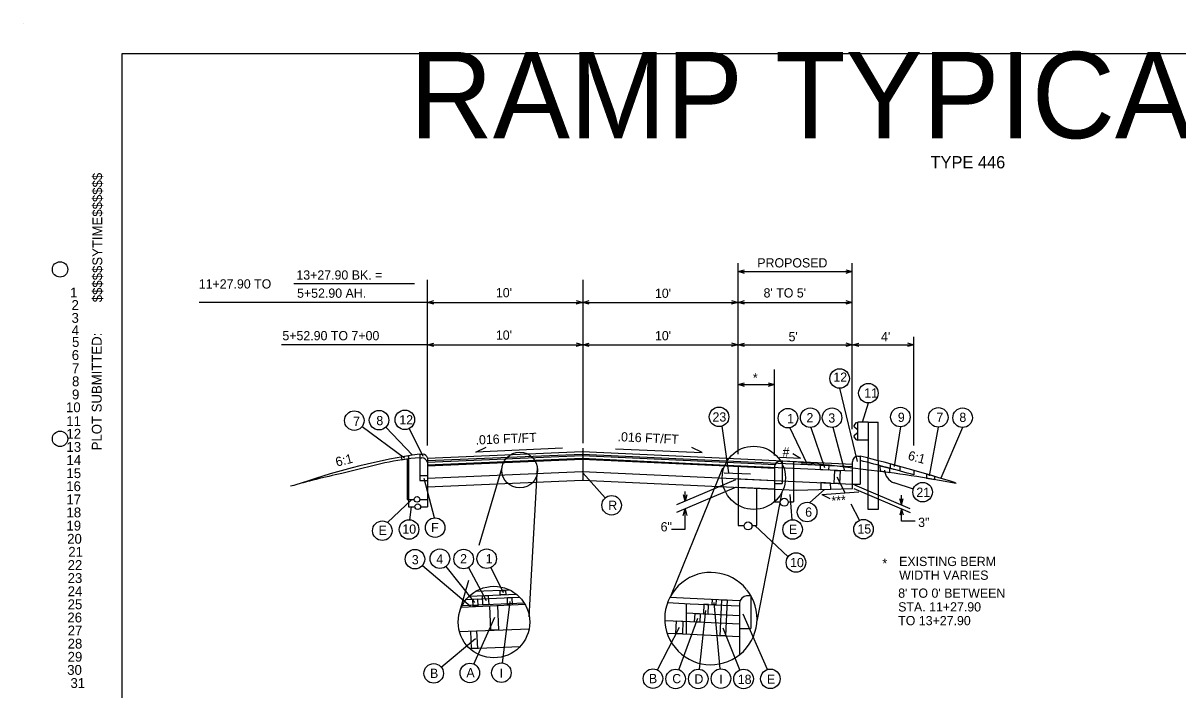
# Model space of a CAD drawing. Extents: x -210 to 558, y -150 to 205.
# Drawn here: x 417 to 491.9, y -105.6 to -62.3 of the extents above; entities that cross this region are included whole.
import ezdxf

# ---------------------------------------------------------------- set-up
doc = ezdxf.new("R2010")
doc.units = 0
for name, color, linetype in [('Level 1', 7, 'Continuous'), ('Level 10', 7, 'Continuous'), ('Level 11', 7, 'Continuous'), ('Level 12', 7, 'Continuous'), ('Level 13', 7, 'Continuous'), ('Level 14', 7, 'Continuous'), ('Level 15', 7, 'Continuous'), ('Level 16', 7, 'Continuous'), ('Level 17', 7, 'Continuous'), ('Level 18', 7, 'Continuous'), ('Level 19', 7, 'Continuous'), ('Level 2', 7, 'Continuous'), ('Level 20', 7, 'Continuous'), ('Level 21', 7, 'Continuous'), ('Level 22', 7, 'Continuous'), ('Level 23', 7, 'Continuous'), ('Level 24', 7, 'Continuous'), ('Level 25', 7, 'Continuous'), ('Level 26', 7, 'Continuous'), ('Level 27', 7, 'Continuous'), ('Level 28', 7, 'Continuous'), ('Level 29', 7, 'Continuous'), ('Level 3', 7, 'Continuous'), ('Level 30', 7, 'Continuous'), ('Level 31', 7, 'Continuous'), ('Level 4', 7, 'Continuous'), ('Level 5', 7, 'Continuous'), ('Level 6', 7, 'Continuous'), ('Level 60', 7, 'Continuous'), ('Level 7', 7, 'Continuous'), ('Level 8', 7, 'Continuous'), ('Level 9', 7, 'Continuous')]:
    doc.layers.add(name, color=color, linetype=linetype)

msp = doc.modelspace()

# ---------------------------------------------------------------- linework, layer by layer
at = {"layer": 'Level 1'}
for p, q in [((417.012, -62.346), (417.012, -62.346)), ((557.356, -64.342), (423.408, -64.342)), ((423.408, -64.342), (423.408, -148.31))]:
    msp.add_line(p, q, dxfattribs=at)
for centre in [(419.41, -78.338), (419.41, -89.334)]:
    msp.add_circle(centre, 0.5, dxfattribs=at)
at = {"layer": 'Level 4'}
for p, q in [((463.4, -90.325), (463.4, -77.927)), ((463.4, -78.481), (470.812, -78.481)), ((470.808, -88.7), (470.808, -77.927)), ((442.408, -79.277), (434.587, -79.277)), ((443.243, -89.772), (443.243, -79.016)), ((453.322, -79.016), (453.322, -89.621)), ((443.243, -80.474), (428.444, -80.474)), ((443.243, -80.474), (453.322, -80.474)), ((453.322, -80.474), (463.4, -80.474)), ((463.4, -80.474), (470.812, -80.474)), ((474.808, -89.766), (474.808, -82.721)), ((443.243, -83.229), (433.787, -83.229)), ((443.243, -83.229), (453.322, -83.229)), ((453.322, -83.229), (474.808, -83.229)), ((465.771, -90.414), (465.771, -84.843)), ((463.397, -85.818), (465.771, -85.818)), ((469.987, -86.052), (471.119, -90.807)), ((471.477, -88.258), (471.853, -87.003)), ((439.008, -88.531), (441.765, -90.578)), ((440.545, -88.584), (442.271, -90.4)), ((442.062, -88.667), (442.951, -90.466)), ((462.337, -88.519), (462.773, -91.547)), ((466.763, -88.61), (467.866, -90.932)), ((468.131, -88.593), (469.015, -91.201)), ((469.541, -88.573), (470.296, -91.411)), ((473.93, -88.552), (473.525, -91.127)), ((476.39, -88.576), (475.801, -91.743)), ((477.968, -88.599), (476.564, -91.891)), ((446.39, -90.191), (447.055, -89.872)), ((461.063, -90.226), (460.398, -89.906)), ((452.016, -89.939), (446.39, -90.191)), ((455.437, -89.974), (461.063, -90.226)), ((467.455, -90.61), (466.956, -90.313)), ((443.696, -94.467), (443.034, -91.907)), ((454.776, -93.175), (453.332, -91.534)), ((463.244, -91.993), (459.409, -93.625)), ((470.352, -92.832), (469.835, -91.829)), ((463.276, -92.477), (459.409, -94.122)), ((459.963, -93.389), (459.963, -92.76)), ((469.013, -92.618), (468.054, -93.476)), ((468.837, -92.94), (471.231, -92.769)), ((470.916, -92.557), (474.561, -94.107)), ((470.947, -92.328), (474.551, -93.862)), ((474.772, -92.594), (473.531, -92.194)), ((442.238, -93.276), (440.663, -94.767)), ((466.758, -92.944), (466.878, -94.587)), ((468.837, -92.94), (469.352, -93.204)), ((471.276, -94.624), (470.738, -93.58)), ((473.997, -93.626), (473.997, -92.996)), ((442.198, -93.739), (442.09, -94.584)), ((459.963, -95.197), (459.963, -93.887)), ((474.007, -94.687), (474.007, -93.872)), ((464.486, -94.97), (466.651, -96.984)), ((474.883, -94.687), (474.007, -94.687)), ((459.087, -95.197), (459.963, -95.197)), ((442.922, -97.555), (446.045, -100.195)), ((444.446, -97.613), (446.294, -99.966)), ((445.9, -97.696), (447.057, -99.824)), ((447.367, -97.686), (448.156, -99.315)), ((448.122, -103.888), (448.611, -99.892)), ((462.236, -104.268), (461.852, -99.952)), ((446.258, -103.952), (447.614, -100.91)), ((459.566, -104.325), (460.784, -100.984)), ((460.903, -104.292), (461.299, -100.481)), ((465.303, -104.308), (463.74, -100.716)), ((458.17, -104.336), (459.602, -101.552)), ((463.52, -104.332), (462.434, -101.631)), ((444.14, -104.156), (446.363, -102.303))]:
    msp.add_line(p, q, dxfattribs=at)
for points in [[(463.82, -78.597), (463.4, -78.481), (463.82, -78.369)], [(463.82, -78.597), (463.4, -78.481), (463.82, -78.369)], [(470.392, -78.365), (470.812, -78.481), (470.392, -78.593)], [(443.663, -80.59), (443.243, -80.474), (443.663, -80.362)], [(452.902, -80.358), (453.322, -80.474), (452.902, -80.586)], [(453.742, -80.59), (453.322, -80.474), (453.742, -80.362)], [(462.98, -80.358), (463.4, -80.474), (462.98, -80.586)], [(463.82, -80.59), (463.4, -80.474), (463.82, -80.362)], [(470.392, -80.358), (470.812, -80.474), (470.392, -80.586)], [(443.663, -83.345), (443.243, -83.229), (443.663, -83.117)], [(452.902, -83.113), (453.322, -83.229), (452.902, -83.341)], [(453.742, -83.345), (453.322, -83.229), (453.742, -83.117)], [(462.98, -83.113), (463.4, -83.229), (462.98, -83.341)], [(463.82, -83.345), (463.4, -83.229), (463.82, -83.117)], [(470.392, -83.113), (470.812, -83.229), (470.392, -83.341)], [(471.232, -83.345), (470.812, -83.229), (471.232, -83.117)], [(474.388, -83.113), (474.808, -83.229), (474.388, -83.341)], [(463.817, -85.934), (463.397, -85.818), (463.817, -85.706)], [(465.351, -85.702), (465.771, -85.818), (465.351, -85.93)], [(460.079, -92.969), (459.963, -93.389), (459.851, -92.969)], [(473.881, -93.206), (473.997, -93.626), (474.109, -93.206)], [(459.847, -94.307), (459.963, -93.887), (460.075, -94.307)], [(474.123, -94.292), (474.007, -93.872), (473.895, -94.292)]]:
    msp.add_lwpolyline(points, dxfattribs=at)
for points in [[(472.624, -91.079), (473.226, -91.243), (473.226, -91.535), (472.635, -91.442)], [(473.284, -90.964), (473.886, -91.128), (473.886, -91.42), (473.284, -91.255)], [(475.627, -91.622), (475.627, -91.888), (476.162, -91.978), (476.162, -91.78)]]:
    msp.add_lwpolyline(points, close=True, dxfattribs=at)
for centre in [(469.988, -85.418), (471.854, -86.369), (438.5, -88.151), (440.108, -88.124), (441.782, -88.098), (462.164, -87.909), (466.634, -87.989), (468.081, -87.961), (469.496, -87.961), (473.931, -87.918), (476.392, -87.941), (477.969, -87.965), (475.374, -92.794), (455.195, -93.65), (467.879, -94.086), (440.318, -95.298), (442.052, -95.216), (443.745, -95.1), (466.94, -95.218), (471.54, -95.201), (442.437, -97.145), (444.055, -97.115), (445.597, -97.139), (447.091, -97.115), (467.158, -97.365), (443.653, -104.562), (446, -104.531), (448.045, -104.517), (457.88, -104.9), (459.349, -104.921), (460.819, -104.921), (462.289, -104.9), (463.757, -104.92), (465.497, -104.912)]:
    msp.add_circle(centre, 0.634, dxfattribs=at)
msp.add_arc((473.861, -91.285), 0.967, 184.63452, 250.04639, dxfattribs=at)
at = {"layer": 'Level 6'}
for p, q in [((441.934, -90.638), (441.934, -93.276)), ((442.743, -90.56), (442.743, -92.038)), ((442.743, -90.56), (442.879, -90.56)), ((443.243, -90.842), (453.277, -90.417)), ((443.243, -91.082), (453.277, -90.657)), ((453.277, -90.417), (463.577, -90.896)), ((453.277, -90.657), (463.577, -91.137)), ((453.322, -89.934), (453.322, -92.019)), ((443.243, -90.862), (443.243, -93.276)), ((463.577, -90.896), (465.805, -91)), ((463.577, -91.137), (465.771, -91.239)), ((465.771, -91.112), (465.771, -93.426)), ((466.092, -90.781), (466.271, -90.781)), ((466.271, -90.781), (466.271, -92.239)), ((466.991, -90.833), (466.991, -93.426)), ((442.743, -92.038), (443.243, -92.038)), ((443.243, -91.88), (453.277, -91.455)), ((443.243, -92.446), (453.277, -92.021)), ((453.277, -91.455), (463.564, -91.934)), ((453.277, -92.021), (463.577, -92.5)), ((463.577, -91.934), (465.771, -92.036)), ((463.577, -92.5), (465.771, -92.603)), ((465.771, -92.239), (466.271, -92.239)), ((441.934, -93.276), (442.388, -93.276)), ((442.752, -93.276), (443.243, -93.276)), ((465.771, -93.426), (466.149, -93.426)), ((466.651, -93.426), (466.991, -93.426)), ((445.766, -99.757), (449.226, -99.61)), ((458.978, -99.623), (460.29, -99.684)), ((463.957, -99.515), (464.218, -99.515)), ((464.218, -99.515), (464.218, -101.642)), ((445.456, -100.251), (449.577, -100.077)), ((458.826, -99.967), (460.29, -100.035)), ((460.033, -100.023), (460.033, -102.012)), ((460.29, -99.684), (463.489, -99.833)), ((460.29, -100.035), (463.489, -100.184)), ((463.489, -99.997), (463.489, -103.372)), ((458.643, -101.12), (460.271, -101.196)), ((460.039, -100.638), (463.489, -100.799)), ((445.325, -101.851), (449.842, -101.66)), ((460.29, -101.197), (463.489, -101.346)), ((463.489, -101.642), (464.218, -101.642)), ((458.796, -101.953), (460.29, -102.023)), ((460.29, -102.023), (463.489, -102.172)), ((446.009, -102.955), (449.254, -102.817))]:
    msp.add_line(p, q, dxfattribs=at)
for centre, radius in [((442.57, -93.265), 0.183), ((466.399, -93.45), 0.257)]:
    msp.add_circle(centre, radius, dxfattribs=at)
for centre, radius, start, end in [((443.889, -105.775), 15.258, 94.30571, 102.86857), ((442.849, -90.967), 0.408, 14.97536, 85.79093), ((459.798, -175.158), 86.442, 102.90634, 104.82046), ((466.162, -91.17), 0.395, 100.20654, 171.53644), ((461.03, -167.839), 77.236, 82.0675, 86.10885), ((462.657, -170.865), 80.034, 79.27032, 83.52075), ((445.323, -129.415), 38.586, 101.4135, 106.49516), ((464.059, -100.083), 0.576, 100.20654, 171.53644)]:
    msp.add_arc(centre, radius, start, end, dxfattribs=at)
at = {"layer": 'Level 60'}
for points in [[(441.594, -90.69), (441.775, -90.664), (441.981, -90.637), (442.032, -90.63), (442.007, -90.441), (441.532, -90.523)], [(467.557, -90.985), (467.563, -90.843), (468.166, -90.871), (468.159, -91.013)], [(468.743, -91.339), (468.756, -91.041), (469.289, -91.066), (469.275, -91.364)], [(469.643, -92.217), (469.682, -91.383), (470.028, -91.399), (469.989, -92.233)], [(468.777, -92.624), (469.424, -92.606), (469.402, -92.206), (468.764, -92.176)], [(446.846, -100.116), (446.821, -99.519), (447.196, -99.503), (447.222, -100.1)], [(447.97, -99.47), (447.958, -99.186), (448.31, -99.172), (448.322, -99.455)], [(448.451, -100.125), (448.43, -99.644), (448.73, -99.631), (448.75, -100.112)], [(446.221, -100.219), (446.2, -99.738), (446.489, -99.726), (446.51, -100.207)], [(447.367, -101.765), (447.3, -100.173), (447.784, -100.153), (447.851, -101.744)], [(461.187, -100.075), (461.158, -100.696), (461.451, -100.71), (461.48, -100.088)], [(461.73, -100.102), (461.747, -99.752), (461.97, -99.762), (461.954, -100.112)], [(462.228, -102.113), (462.336, -99.779), (462.683, -99.795), (462.575, -102.129)], [(460.583, -101.214), (460.608, -100.668), (460.945, -100.684), (460.919, -101.23)], [(446.106, -102.951), (446.058, -101.82), (446.436, -101.804), (446.484, -102.935)], [(459.361, -101.978), (459.399, -101.154), (459.826, -101.174), (459.788, -101.998)]]:
    msp.add_lwpolyline(points, close=True, dxfattribs=at)
at = {"layer": 'Level 7'}
for p, q in [((470.931, -88.472), (471.079, -88.268)), ((471.079, -88.268), (471.166, -88.253)), ((471.833, -88.253), (471.166, -88.253)), ((471.166, -89.419), (471.166, -88.253)), ((471.833, -88.253), (471.833, -90.503)), ((471.833, -88.253), (472.5, -88.253)), ((472.5, -90.755), (472.5, -88.253)), ((471.136, -88.727), (470.947, -88.58)), ((470.947, -89.092), (471.136, -88.944)), ((471.079, -89.404), (470.931, -89.199)), ((471.079, -89.404), (471.166, -89.419)), ((471.833, -89.419), (471.166, -89.419)), ((442.026, -90.437), (442.026, -93.739)), ((442.743, -90.323), (442.743, -91.709)), ((442.743, -90.323), (442.964, -90.323)), ((453.277, -90.178), (443.243, -90.603)), ((443.243, -90.745), (453.277, -90.32)), ((443.243, -90.568), (443.243, -93.739)), ((453.277, -90.619), (443.243, -91.044)), ((463.577, -90.658), (453.277, -90.178)), ((453.277, -90.32), (463.577, -90.8)), ((463.577, -91.099), (453.277, -90.619)), ((470.83, -90.995), (463.577, -90.658)), ((467.455, -90.61), (466.093, -90.546)), ((471.175, -90.455), (471.33, -90.455)), ((471.33, -90.455), (471.33, -92.279)), ((471.833, -93.919), (471.833, -90.503)), ((446.611, -96.227), (448.087, -91.196)), ((449.857, -100.884), (450.388, -91.214)), ((462.39, -91.242), (460.535, -95.831)), ((463.4, -91.091), (463.4, -92.493)), ((463.577, -90.8), (470.83, -91.138)), ((470.83, -91.437), (463.577, -91.099)), ((470.83, -92.567), (470.83, -90.825)), ((472.5, -90.755), (472.5, -93.919)), ((474.808, -91.386), (474.808, -91.678)), ((442.743, -91.709), (443.243, -91.709)), ((462.506, -91.535), (464.198, -91.614)), ((463.4, -91.926), (470.83, -92.272)), ((465.782, -92.603), (463.4, -92.493)), ((463.4, -92.493), (463.4, -94.97)), ((464.62, -94.97), (464.62, -92.55)), ((466.247, -92.788), (465.585, -96.203)), ((465.771, -92.603), (467.19, -92.669)), ((467.19, -92.669), (470.83, -92.567)), ((470.83, -92.279), (471.33, -92.279)), ((442.026, -93.739), (442.434, -93.739)), ((442.799, -93.739), (443.243, -93.739)), ((472.5, -93.919), (471.833, -93.919)), ((463.4, -94.97), (463.774, -94.97)), ((464.324, -94.97), (464.62, -94.97)), ((460.535, -95.831), (459.065, -99.465)), ((465.585, -96.203), (464.624, -101.169)), ((445.322, -100.616), (445.939, -98.515)), ((445.952, -99.556), (449.024, -99.426)), ((448.613, -99.159), (446.339, -99.255)), ((449.533, -100.003), (445.493, -100.174))]:
    msp.add_line(p, q, dxfattribs=at)
for centre, radius in [((464.423, -91.864), 2.053), ((449.236, -91.362), 1.161), ((442.617, -93.742), 0.183), ((464.046, -94.989), 0.257), ((447.561, -101.229), 2.322)]:
    msp.add_circle(centre, radius, dxfattribs=at)
for centre, radius, start, end in [((470.994, -88.518), 0.0781, 144.08393, 232.1285), ((470.994, -89.154), 0.0781, 127.8715, 215.91607), ((471.088, -88.883), 0.0781, 307.8715, 360), ((449.137, -132.768), 42.924, 98.56629, 109.15776), ((442.907, -90.67), 0.351, 16.82618, 80.73672), ((471.201, -90.825), 0.371, 94.06959, 179.94015), ((443.267, -202.27), 115.282, 72.7225, 75.91119), ((443.267, -202.562), 115.282, 74.12174, 75.91119), ((461.635, -101.002), 2.994, 39.26715, 38.73701)]:
    msp.add_arc(centre, radius, start, end, dxfattribs=at)

# ---------------------------------------------------------------- texts
at = {"layer": 'Level 1'}
for s, height, p in [('RAMP TYPICAL SECTIONS', 5.6, (442.087, -69.82)), ('TYPE 446', 0.795, (475.889, -71.777)), ('1', 0.638, (420.064, -80.154))]:
    msp.add_text(s, height=height, dxfattribs=at).set_placement(p)
for s, p in [('$$$$$SYTIME$$$$$$', (422.148, -80.467)), ('PLOT SUBMITTED:', (422.11, -90.081))]:
    msp.add_text(s, height=0.63833, rotation=90, dxfattribs=at).set_placement(p)
at = {"layer": 'Level 10'}
msp.add_text('10', height=0.6378, dxfattribs=at).set_placement((419.797, -87.607))
at = {"layer": 'Level 11'}
msp.add_text('11', height=0.6409, dxfattribs=at).set_placement((419.812, -88.508))
at = {"layer": 'Level 12'}
msp.add_text('12', height=0.6384, dxfattribs=at).set_placement((419.827, -89.325))
at = {"layer": 'Level 13'}
msp.add_text('13', height=0.6384, dxfattribs=at).set_placement((419.827, -90.18))
at = {"layer": 'Level 14'}
msp.add_text('14', height=0.6409, dxfattribs=at).set_placement((419.827, -91.035))
at = {"layer": 'Level 15'}
msp.add_text('15', height=0.6378, dxfattribs=at).set_placement((419.827, -91.883))
at = {"layer": 'Level 16'}
msp.add_text('16', height=0.6384, dxfattribs=at).set_placement((419.812, -92.73))
at = {"layer": 'Level 17'}
msp.add_text('17', height=0.6384, dxfattribs=at).set_placement((419.827, -93.585))
at = {"layer": 'Level 18'}
msp.add_text('18', height=0.6409, dxfattribs=at).set_placement((419.827, -94.433))
at = {"layer": 'Level 19'}
msp.add_text('19', height=0.6378, dxfattribs=at).set_placement((419.827, -95.288))
at = {"layer": 'Level 2'}
msp.add_text('2', height=0.641, dxfattribs=at).set_placement((420.156, -80.971))
at = {"layer": 'Level 20'}
msp.add_text('20', height=0.6384, dxfattribs=at).set_placement((419.873, -96.143))
at = {"layer": 'Level 21'}
msp.add_text('21', height=0.6414, dxfattribs=at).set_placement((419.942, -96.991))
at = {"layer": 'Level 22'}
msp.add_text('22', height=0.6384, dxfattribs=at).set_placement((419.904, -97.846))
at = {"layer": 'Level 23'}
msp.add_text('23', height=0.6384, dxfattribs=at).set_placement((419.904, -98.694))
at = {"layer": 'Level 24'}
msp.add_text('24', height=0.6414, dxfattribs=at).set_placement((419.904, -99.549))
at = {"layer": 'Level 25'}
msp.add_text('25', height=0.6384, dxfattribs=at).set_placement((419.904, -100.396))
at = {"layer": 'Level 26'}
msp.add_text('26', height=0.6384, dxfattribs=at).set_placement((419.888, -101.252))
at = {"layer": 'Level 27'}
msp.add_text('27', height=0.6419, dxfattribs=at).set_placement((419.904, -102.099))
at = {"layer": 'Level 28'}
msp.add_text('28', height=0.6384, dxfattribs=at).set_placement((419.904, -102.947))
at = {"layer": 'Level 29'}
msp.add_text('29', height=0.6378, dxfattribs=at).set_placement((419.904, -103.802))
at = {"layer": 'Level 3'}
msp.add_text('3', height=0.638, dxfattribs=at).set_placement((420.156, -81.804))
at = {"layer": 'Level 30'}
msp.add_text('30', height=0.6409, dxfattribs=at).set_placement((419.873, -104.657))
at = {"layer": 'Level 31'}
msp.add_text('31', height=0.6378, dxfattribs=at).set_placement((420.087, -105.505))
at = {"layer": 'Level 4'}
for s, height, p in [('PROPOSED', 0.6, (464.649, -78.21)), ('13+27.90 BK. =', 0.6, (434.743, -78.999)), ('11+27.90 TO', 0.6, (428.41, -79.577)), ('5+52.90 AH.', 0.6, (434.787, -80.177)), ("10'", 0.6, (447.688, -80.145)), ("10'", 0.6, (458.009, -80.183)), ("8' TO 5'", 0.6, (465.054, -80.16)), ('4', 0.634, (420.163, -82.605)), ('5+52.90 TO 7+00', 0.6, (433.836, -82.937)), ("10'", 0.6, (447.688, -82.9)), ("10'", 0.6, (458.009, -82.939)), ("5'", 0.6, (466.676, -83.004)), ("4'", 0.6, (472.673, -83.004)), ('*', 0.6, (464.36, -85.671)), ('12', 0.6, (469.583, -85.633)), ('11', 0.6, (471.589, -86.657)), ('23', 0.6, (461.742, -88.214)), ('2', 0.6, (467.838, -88.26)), ('9', 0.6, (473.765, -88.234)), ('7', 0.6, (476.269, -88.238)), ('8', 0.6, (477.758, -88.238)), ('7', 0.6, (438.427, -88.491)), ('8', 0.6, (439.931, -88.452)), ('12', 0.6, (441.421, -88.399)), ('1', 0.6, (466.583, -88.318)), ('3', 0.6, (469.256, -88.28)), ('#', 0.6, (466.283, -90.492)), ('21', 0.6, (474.969, -93.102)), ('R', 0.6, (454.979, -93.95)), ('6', 0.6, (467.755, -94.389)), ('E', 0.6, (440.071, -95.571)), ('10', 0.6, (441.618, -95.493)), ('F', 0.6, (443.485, -95.391)), ('6"', 0.6, (458.376, -95.344)), ('E', 0.6, (466.7, -95.507)), ('15', 0.6, (471.144, -95.481)), ('3"', 0.6, (475.084, -95.054)), ('3', 0.6, (442.233, -97.481)), ('4', 0.6, (443.82, -97.44)), ('2', 0.6, (445.366, -97.42)), ('1', 0.6, (447.024, -97.42)), ('10', 0.6, (466.775, -97.665)), ('*', 0.6, (472.764, -97.721)), ('EXISTING BERM', 0.6, (473.851, -97.593)), ('WIDTH VARIES', 0.6, (473.851, -98.485)), ("8' TO 0' BETWEEN", 0.6, (473.79, -99.651)), ('STA. 11+27.90', 0.6, (473.79, -100.543)), ('TO 13+27.90', 0.6, (473.79, -101.435)), ('B', 0.6, (443.413, -104.856)), ('A', 0.6, (445.773, -104.816)), ('I', 0.6, (447.93, -104.846)), ('B', 0.6, (457.619, -105.198)), ('C', 0.6, (459.13, -105.198)), ('D', 0.6, (460.57, -105.222)), ('I', 0.6, (462.186, -105.234)), ('18', 0.6, (463.38, -105.245)), ('E', 0.6, (465.271, -105.234))]:
    msp.add_text(s, height=height, dxfattribs=at).set_placement(p)
for s, rotation, p in [('.016 FT/FT', 2.57074, (446.381, -89.714)), ('.016 FT/FT', 357.33406, (455.571, -89.484)), ('6:1', 13.75246, (437.365, -91.141)), ('6:1', 344.83795, (474.379, -90.675)), ('***', 4.07739, (469.481, -93.66))]:
    msp.add_text(s, height=0.6, rotation=rotation, dxfattribs=at).set_placement(p)
at = {"layer": 'Level 5'}
msp.add_text('5', height=0.641, dxfattribs=at).set_placement((420.186, -83.369))
at = {"layer": 'Level 6'}
msp.add_text('6', height=0.638, dxfattribs=at).set_placement((420.171, -84.217))
at = {"layer": 'Level 7'}
msp.add_text('7', height=0.638, dxfattribs=at).set_placement((420.186, -85.072))
at = {"layer": 'Level 8'}
msp.add_text('8', height=0.641, dxfattribs=at).set_placement((420.186, -85.919))
at = {"layer": 'Level 9'}
msp.add_text('9', height=0.638, dxfattribs=at).set_placement((420.186, -86.774))

doc.saveas('drawing.dxf')
